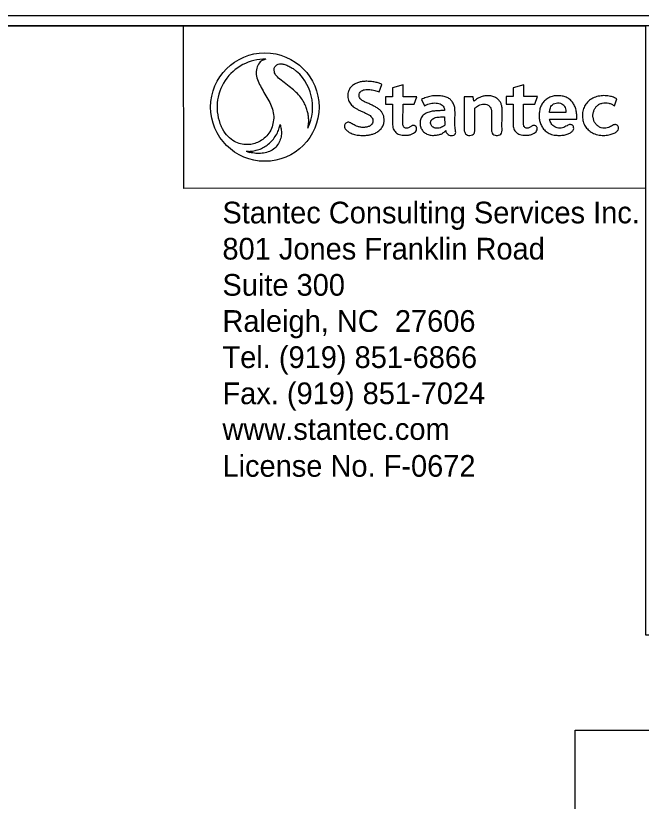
# Model space of a CAD drawing. Extents: x 2320980 to 2456309, y 595047 to 606177.
# Drawn here: x 2455971.04 to 2456001.89, y 596479.87 to 596518.57 of the extents above; entities that cross this region are included whole.
import ezdxf

# ---------------------------------------------------------------- set-up
doc = ezdxf.new("R2010")
doc.units = 0
for name, color, linetype in [('Prop Dimension', 7, 'Continuous'), ('Scratch_Level_0', 7, 'Continuous'), ('Sheet Data Text CELL', 7, 'Continuous'), ('Sheet Plan CELL', 7, 'Continuous'), ('Sheet Plot Border Inside CELL', 7, 'Continuous')]:
    doc.layers.add(name, color=color, linetype=linetype)

msp = doc.modelspace()

# ---------------------------------------------------------------- linework, layer by layer
at = {"layer": 'Prop Dimension'}
msp.add_lwpolyline([(2455998.637, 596483.366), (2456042.107, 596483.366), (2456042.107, 596479.09), (2455998.637, 596479.09)], close=True, dxfattribs=at)
at = {"layer": 'Scratch_Level_0'}
msp.add_lwpolyline([(2455979.323, 596518.076), (2456002.097, 596518.079), (2456002.098, 596510.07), (2455979.324, 596510.067)], close=True, dxfattribs=at)
at = {"layer": 'Sheet Data Text CELL'}
for p, q in [((2455988.965, 596514.819), (2455989.095, 596515.192)), ((2455990.145, 596515.169), (2455989.619, 596515.022)), ((2455989.619, 596515.022), (2455989.619, 596514.585)), ((2455990.145, 596514.585), (2455990.145, 596515.169)), ((2455996.092, 596515.17), (2455995.566, 596515.023)), ((2455995.566, 596515.023), (2455995.566, 596514.586)), ((2455996.092, 596514.586), (2455996.092, 596515.17)), ((2455989.619, 596514.585), (2455989.285, 596514.585)), ((2455989.285, 596514.585), (2455989.285, 596514.219)), ((2455990.826, 596514.585), (2455990.145, 596514.585)), ((2455990.699, 596514.219), (2455990.826, 596514.585)), ((2455993.606, 596514.584), (2455993.163, 596514.584)), ((2455993.163, 596514.584), (2455993.163, 596512.906)), ((2455993.635, 596514.362), (2455993.606, 596514.584)), ((2455995.566, 596514.586), (2455995.231, 596514.586)), ((2455995.231, 596514.586), (2455995.231, 596514.22)), ((2455996.773, 596514.586), (2455996.092, 596514.586)), ((2455996.645, 596514.22), (2455996.773, 596514.586)), ((2455989.285, 596514.219), (2455989.623, 596514.219)), ((2455990.135, 596513.294), (2455990.142, 596514.219)), ((2455990.142, 596514.219), (2455990.699, 596514.219)), ((2455991.046, 596514.451), (2455991.206, 596514.141)), ((2455995.231, 596514.22), (2455995.57, 596514.22)), ((2455996.082, 596513.295), (2455996.089, 596514.22)), ((2455996.089, 596514.22), (2455996.645, 596514.22)), ((2456000.57, 596514.131), (2456000.686, 596514.475)), ((2455993.679, 596512.906), (2455993.679, 596514.014)), ((2455998.174, 596513.803), (2455997.371, 596513.803)), ((2455992.195, 596513.591), (2455992.196, 596513.176)), ((2455997.371, 596513.481), (2455998.707, 596513.481))]:
    msp.add_line(p, q, dxfattribs=at)
for points in [[(2455983.379, 596516.428), (2455983.379, 596516.428)], [(2455984.732, 596515.965), (2455984.732, 596515.965)]]:
    msp.add_lwpolyline(points, dxfattribs=at)
msp.add_circle((2455983.328, 596514.072), 2.673, dxfattribs=at)
for start, end in [(88.7738, 203.6916), (88.7673, 88.7738), (333.7886, 53.4398), (247.1256, 251.4651)]:
    msp.add_arc((2455983.328, 596514.072), 2.357, start, end, dxfattribs=at)
for points, degree in [([(2455983.379, 596516.428), (2455983.322, 596516.416), (2455983.188, 596516.388), (2455983.013, 596516.209), (2455982.883, 596515.916), (2455982.9, 596515.587), (2455983.016, 596515.269), (2455983.192, 596514.96), (2455983.374, 596514.619), (2455983.576, 596514.297), (2455983.716, 596513.97), (2455983.782, 596513.614), (2455983.739, 596513.258), (2455983.635, 596512.931), (2455983.434, 596512.634), (2455983.17, 596512.423), (2455982.894, 596512.299), (2455982.644, 596512.222), (2455982.365, 596512.222), (2455982.055, 596512.265), (2455981.749, 596512.405), (2455981.423, 596512.681), (2455981.266, 596512.952), (2455981.17, 596513.125)], 3), ([(2455983.379, 596516.428), (2455983.379, 596516.428), (2455983.379, 596516.428), (2455983.379, 596516.428)], 2), ([(2455985.442, 596513.031), (2455985.463, 596513.114), (2455985.498, 596513.269), (2455985.491, 596513.518), (2455985.467, 596513.737), (2455985.403, 596513.94), (2455985.327, 596514.175), (2455985.194, 596514.43), (2455985.004, 596514.67), (2455984.756, 596514.923), (2455984.446, 596515.148), (2455984.127, 596515.409), (2455983.871, 596515.601), (2455983.781, 596515.827), (2455983.78, 596515.999), (2455983.865, 596516.115), (2455983.978, 596516.196), (2455984.129, 596516.21), (2455984.307, 596516.176), (2455984.513, 596516.089), (2455984.655, 596516.009), (2455984.732, 596515.965)], 3), ([(2455989.095, 596515.192), (2455989.072, 596515.203), (2455988.968, 596515.253), (2455988.77, 596515.305), (2455988.527, 596515.335), (2455988.306, 596515.346), (2455988.121, 596515.328), (2455987.945, 596515.291), (2455987.775, 596515.224), (2455987.611, 596515.111), (2455987.493, 596514.961), (2455987.426, 596514.809), (2455987.411, 596514.667), (2455987.418, 596514.536), (2455987.446, 596514.411), (2455987.499, 596514.308), (2455987.563, 596514.215), (2455987.642, 596514.13), (2455987.738, 596514.053), (2455987.856, 596513.982), (2455988.003, 596513.906), (2455988.165, 596513.832), (2455988.33, 596513.762), (2455988.466, 596513.692), (2455988.566, 596513.607), (2455988.635, 596513.527), (2455988.659, 596513.429), (2455988.656, 596513.336), (2455988.618, 596513.233), (2455988.533, 596513.148), (2455988.398, 596513.09), (2455988.238, 596513.066), (2455988.06, 596513.074), (2455987.903, 596513.107), (2455987.776, 596513.17), (2455987.673, 596513.212), (2455987.604, 596513.277), (2455987.538, 596513.302), (2455987.478, 596513.328), (2455987.413, 596513.324), (2455987.348, 596513.304), (2455987.293, 596513.256), (2455987.257, 596513.188), (2455987.254, 596513.113), (2455987.265, 596513.039), (2455987.323, 596512.961), (2455987.435, 596512.849), (2455987.633, 596512.752), (2455987.878, 596512.687), (2455988.127, 596512.674), (2455988.341, 596512.68), (2455988.528, 596512.704), (2455988.692, 596512.754), (2455988.863, 596512.831), (2455989.027, 596512.96), (2455989.154, 596513.12), (2455989.208, 596513.309), (2455989.215, 596513.479), (2455989.194, 596513.633), (2455989.133, 596513.757), (2455989.06, 596513.881), (2455988.932, 596513.986), (2455988.787, 596514.083), (2455988.627, 596514.16), (2455988.454, 596514.241), (2455988.274, 596514.318), (2455988.121, 596514.399), (2455988.018, 596514.492), (2455987.974, 596514.583), (2455987.966, 596514.678), (2455987.994, 596514.765), (2455988.053, 596514.841), (2455988.135, 596514.895), (2455988.243, 596514.934), (2455988.372, 596514.944), (2455988.5, 596514.939), (2455988.627, 596514.919), (2455988.75, 596514.892), (2455988.865, 596514.858), (2455988.934, 596514.831), (2455988.965, 596514.819)], 3), ([(2455992.247, 596512.915), (2455992.248, 596512.897), (2455992.252, 596512.854), (2455992.295, 596512.79), (2455992.357, 596512.718), (2455992.469, 596512.666), (2455992.587, 596512.67), (2455992.697, 596512.694), (2455992.74, 596512.781), (2455992.742, 596512.868), (2455992.717, 596512.985), (2455992.69, 596513.307), (2455992.71, 596513.647), (2455992.704, 596514.015), (2455992.662, 596514.193), (2455992.562, 596514.353), (2455992.454, 596514.476), (2455992.276, 596514.566), (2455992.056, 596514.623), (2455991.795, 596514.64), (2455991.531, 596514.614), (2455991.277, 596514.555), (2455991.121, 596514.485), (2455991.046, 596514.451)], 3), ([(2455993.679, 596514.014), (2455993.687, 596514.022), (2455993.723, 596514.055), (2455993.809, 596514.107), (2455993.921, 596514.181), (2455994.063, 596514.224), (2455994.207, 596514.223), (2455994.346, 596514.178), (2455994.441, 596514.079), (2455994.493, 596513.961), (2455994.52, 596513.801), (2455994.503, 596513.562), (2455994.515, 596513.259), (2455994.499, 596513.006), (2455994.51, 596512.832), (2455994.57, 596512.738), (2455994.675, 596512.672), (2455994.797, 596512.674), (2455994.913, 596512.702), (2455995.008, 596512.774), (2455995.035, 596512.912), (2455995.015, 596513.156), (2455995.028, 596513.456), (2455995.021, 596513.786), (2455995.033, 596513.996), (2455995.005, 596514.178), (2455994.948, 596514.306), (2455994.857, 596514.437), (2455994.711, 596514.54), (2455994.527, 596514.627), (2455994.317, 596514.632), (2455994.128, 596514.621), (2455993.958, 596514.565), (2455993.807, 596514.495), (2455993.706, 596514.415), (2455993.653, 596514.375), (2455993.635, 596514.362)], 3), ([(2455998.707, 596513.481), (2455998.709, 596513.532), (2455998.713, 596513.66), (2455998.69, 596513.866), (2455998.638, 596514.097), (2455998.527, 596514.275), (2455998.402, 596514.429), (2455998.243, 596514.538), (2455998.041, 596514.618), (2455997.815, 596514.633), (2455997.593, 596514.629), (2455997.382, 596514.562), (2455997.201, 596514.459), (2455997.044, 596514.309), (2455996.937, 596514.128), (2455996.877, 596513.929), (2455996.854, 596513.726), (2455996.851, 596513.507), (2455996.9, 596513.305), (2455996.98, 596513.108), (2455997.102, 596512.939), (2455997.288, 596512.805), (2455997.519, 596512.691), (2455997.788, 596512.677), (2455998.033, 596512.679), (2455998.241, 596512.724), (2455998.405, 596512.803), (2455998.524, 596512.907), (2455998.568, 596513.019), (2455998.548, 596513.11), (2455998.503, 596513.183), (2455998.431, 596513.203), (2455998.36, 596513.213), (2455998.278, 596513.187), (2455998.181, 596513.126), (2455998.07, 596513.059), (2455997.934, 596513.028), (2455997.808, 596513.025), (2455997.684, 596513.057), (2455997.581, 596513.128), (2455997.479, 596513.211), (2455997.419, 596513.323), (2455997.382, 596513.413), (2455997.374, 596513.464), (2455997.371, 596513.481)], 3), ([(2456000.686, 596514.475), (2456000.642, 596514.5), (2456000.532, 596514.561), (2456000.319, 596514.617), (2456000.053, 596514.645), (2455999.77, 596514.612), (2455999.499, 596514.524), (2455999.276, 596514.374), (2455999.115, 596514.172), (2455999.015, 596513.938), (2455998.98, 596513.676), (2455999.001, 596513.411), (2455999.091, 596513.174), (2455999.225, 596512.992), (2455999.411, 596512.833), (2455999.666, 596512.714), (2455999.965, 596512.667), (2456000.239, 596512.685), (2456000.466, 596512.745), (2456000.645, 596512.827), (2456000.762, 596512.94), (2456000.768, 596513.047), (2456000.758, 596513.127), (2456000.704, 596513.176), (2456000.649, 596513.209), (2456000.588, 596513.213), (2456000.506, 596513.2), (2456000.433, 596513.136), (2456000.326, 596513.091), (2456000.22, 596513.041), (2456000.067, 596513.029), (2455999.908, 596513.043), (2455999.755, 596513.126), (2455999.64, 596513.242), (2455999.548, 596513.38), (2455999.52, 596513.544), (2455999.496, 596513.706), (2455999.542, 596513.866), (2455999.604, 596514.013), (2455999.695, 596514.13), (2455999.818, 596514.217), (2455999.958, 596514.272), (2456000.122, 596514.285), (2456000.286, 596514.27), (2456000.443, 596514.22), (2456000.529, 596514.16), (2456000.57, 596514.131)], 3), ([(2455989.623, 596514.219), (2455989.621, 596513.892), (2455989.62, 596513.547), (2455989.624, 596513.162), (2455989.641, 596513.07), (2455989.677, 596512.944), (2455989.749, 596512.858), (2455989.821, 596512.791), (2455989.898, 596512.74), (2455990.02, 596512.698), (2455990.188, 596512.679), (2455990.362, 596512.687), (2455990.536, 596512.711), (2455990.668, 596512.778), (2455990.765, 596512.856), (2455990.81, 596512.946), (2455990.815, 596513.025), (2455990.801, 596513.092), (2455990.766, 596513.131), (2455990.724, 596513.156), (2455990.675, 596513.165), (2455990.623, 596513.166), (2455990.57, 596513.152), (2455990.523, 596513.114), (2455990.47, 596513.074), (2455990.405, 596513.046), (2455990.336, 596513.024), (2455990.264, 596513.032), (2455990.202, 596513.066), (2455990.154, 596513.114), (2455990.133, 596513.197), (2455990.134, 596513.256), (2455990.135, 596513.294)], 3), ([(2455991.206, 596514.141), (2455991.23, 596514.154), (2455991.303, 596514.193), (2455991.422, 596514.23), (2455991.566, 596514.267), (2455991.702, 596514.276), (2455991.844, 596514.271), (2455991.972, 596514.231), (2455992.083, 596514.167), (2455992.161, 596514.074), (2455992.194, 596513.979), (2455992.194, 596513.92), (2455992.194, 596513.901)], 3), ([(2455995.57, 596514.22), (2455995.568, 596513.892), (2455995.567, 596513.548), (2455995.57, 596513.163), (2455995.588, 596513.07), (2455995.624, 596512.944), (2455995.695, 596512.859), (2455995.768, 596512.792), (2455995.844, 596512.741), (2455995.967, 596512.698), (2455996.135, 596512.68), (2455996.309, 596512.687), (2455996.482, 596512.711), (2455996.614, 596512.778), (2455996.711, 596512.857), (2455996.757, 596512.947), (2455996.762, 596513.026), (2455996.747, 596513.092), (2455996.712, 596513.132), (2455996.671, 596513.156), (2455996.621, 596513.165), (2455996.569, 596513.166), (2455996.517, 596513.153), (2455996.47, 596513.115), (2455996.417, 596513.075), (2455996.351, 596513.047), (2455996.282, 596513.025), (2455996.211, 596513.033), (2455996.149, 596513.067), (2455996.1, 596513.115), (2455996.08, 596513.198), (2455996.081, 596513.257), (2455996.082, 596513.295)], 3), ([(2455997.371, 596513.803), (2455997.371, 596513.82), (2455997.371, 596513.861), (2455997.376, 596513.939), (2455997.402, 596514.04), (2455997.465, 596514.146), (2455997.562, 596514.231), (2455997.695, 596514.278), (2455997.837, 596514.282), (2455997.97, 596514.241), (2455998.083, 596514.169), (2455998.139, 596514.046), (2455998.167, 596513.922), (2455998.172, 596513.84), (2455998.174, 596513.803)], 3), ([(2455992.194, 596513.901), (2455992.16, 596513.9), (2455992.05, 596513.898), (2455991.859, 596513.889), (2455991.632, 596513.877), (2455991.42, 596513.83), (2455991.224, 596513.749), (2455991.053, 596513.602), (2455990.973, 596513.394), (2455990.984, 596513.198), (2455991.016, 596513.03), (2455991.118, 596512.888), (2455991.266, 596512.758), (2455991.478, 596512.679), (2455991.698, 596512.676), (2455991.902, 596512.702), (2455992.057, 596512.757), (2455992.172, 596512.835), (2455992.22, 596512.887), (2455992.247, 596512.915)], 3), ([(2455992.196, 596513.176), (2455992.183, 596513.165), (2455992.134, 596513.128), (2455992.045, 596513.08), (2455991.92, 596513.028), (2455991.787, 596513.02), (2455991.672, 596513.05), (2455991.592, 596513.102), (2455991.54, 596513.163), (2455991.505, 596513.237), (2455991.5, 596513.316), (2455991.515, 596513.395), (2455991.562, 596513.47), (2455991.643, 596513.518), (2455991.739, 596513.561), (2455991.866, 596513.578), (2455991.996, 596513.585), (2455992.111, 596513.592), (2455992.171, 596513.591), (2455992.195, 596513.591)], 3), ([(2455982.412, 596511.901), (2455982.47, 596511.895), (2455982.606, 596511.882), (2455982.84, 596511.927), (2455983.101, 596511.988), (2455983.336, 596512.125), (2455983.552, 596512.277), (2455983.755, 596512.495), (2455983.923, 596512.737), (2455984.03, 596512.99), (2455984.062, 596513.139), (2455984.078, 596513.21)], 3), ([(2455984.078, 596513.21), (2455984.095, 596513.15), (2455984.139, 596512.997), (2455984.15, 596512.741), (2455984.106, 596512.463), (2455983.963, 596512.211), (2455983.771, 596511.979), (2455983.491, 596511.852), (2455983.194, 596511.784), (2455982.888, 596511.779), (2455982.679, 596511.819), (2455982.579, 596511.838)], 3), ([(2455993.163, 596512.906), (2455993.168, 596512.884), (2455993.179, 596512.834), (2455993.216, 596512.749), (2455993.31, 596512.677), (2455993.441, 596512.676), (2455993.573, 596512.686), (2455993.651, 596512.772), (2455993.679, 596512.847), (2455993.679, 596512.888), (2455993.679, 596512.906)], 3)]:
    msp.add_open_spline(points, degree=degree, dxfattribs=at)
at = {"layer": 'Sheet Plan CELL'}
for points in [[(2455742.104, 596308.076), (2455742.099, 596518.071), (2456002.097, 596518.079), (2456002.099, 596488.066), (2456042.107, 596488.064), (2456042.107, 596308.076)], [(2456042.112, 596518.076), (2455742.104, 596518.076), (2455742.104, 596308.076), (2456042.107, 596308.076)]]:
    msp.add_lwpolyline(points, close=True, dxfattribs=at)
at = {"layer": 'Sheet Plot Border Inside CELL'}
msp.add_lwpolyline([(2455711.407, 596307.574), (2456044.604, 596307.576), (2456044.607, 596518.574), (2455711.407, 596518.574)], close=True, dxfattribs=at)

# ---------------------------------------------------------------- texts
at = {"layer": 'Sheet Data Text CELL'}
for s, height, p in [('Stantec Consulting Services Inc.', 1.06932, (2455981.236, 596508.34)), ('801 Jones Franklin Road', 1.06932, (2455981.236, 596506.559)), ('Suite 300', 1.0693, (2455981.236, 596504.777)), ('Raleigh, NC  27606', 1.06932, (2455981.236, 596502.996)), ('Tel. (919) 851-6866', 1.06932, (2455981.237, 596501.215)), ('Fax. (919) 851-7024', 1.06932, (2455981.237, 596499.433)), ('www.stantec.com', 1.06932, (2455981.237, 596497.673)), ('License No. F-0672', 1.06932, (2455981.237, 596495.857))]:
    msp.add_text(s, height=height, rotation=0.0071, dxfattribs=at).set_placement(p)

doc.saveas('drawing.dxf')
